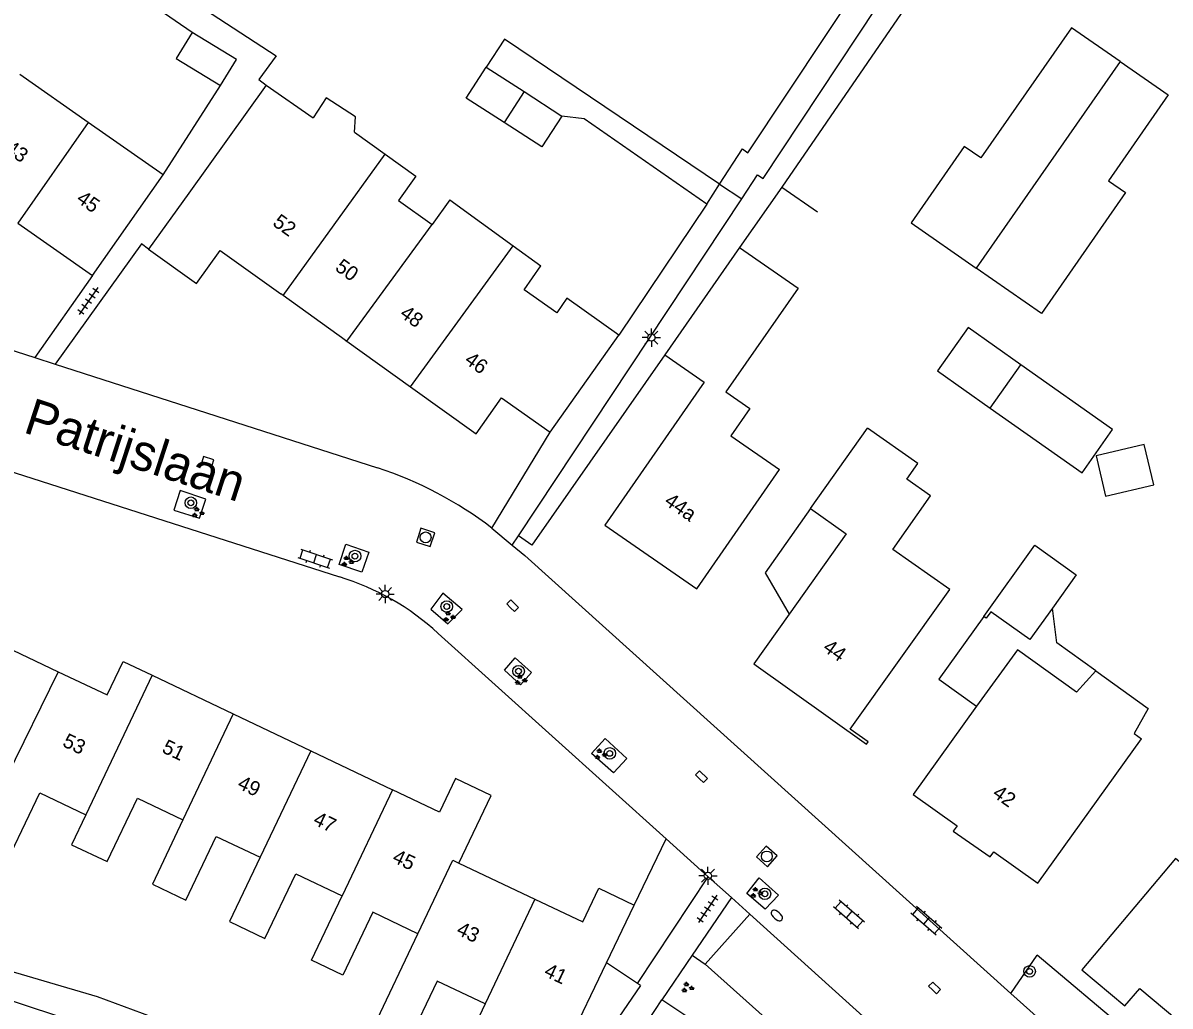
# Model space of a CAD drawing. Extents: x 136000 to 141000, y 400494 to 402006.
# Drawn here: x 137769.2 to 137848.1, y 401752.7 to 401820.4 of the extents above; entities that cross this region are included whole.
import ezdxf

# ---------------------------------------------------------------- set-up
doc = ezdxf.new("R2010")
doc.units = 0
for name, color, linetype in [('gg-afsc-erfafscheiding', 7, 'Continuous'), ('gg-afsc-muur', 7, 'Continuous'), ('gg-anno-huisnummerreeks BGT', 7, 'Continuous'), ('gg-anno-openbare ruimte label', 7, 'Continuous'), ('gg-bbg-bijgebouw', 7, 'Continuous'), ('gg-bbg-gedigitaliseerde bebouwing', 7, 'Continuous'), ('gg-bbg-gedigitaliseerde bijgebouw', 7, 'Continuous'), ('gg-bbg-hoofdgebouw', 7, 'Continuous'), ('gg-bbg-luifel en loopbrug', 7, 'Continuous'), ('gg-bbg-tussenscheiding', 7, 'Continuous'), ('gg-knt-verharding', 7, 'Continuous'), ('gg-knt-verharding nz', 7, 'Continuous'), ('gt-bbg-plantopografie pand', 7, 'Continuous'), ('gt-grn-groengrens', 7, 'Continuous'), ('gt-grn-weggrens', 7, 'Continuous'), ('gt-symb-boom', 7, 'Continuous'), ('gt-symb-brandkraan', 7, 'Continuous'), ('gt-symb-groenvak', 7, 'Continuous'), ('gt-symb-klinker verharding', 7, 'Continuous'), ('gt-symb-kolk', 7, 'Continuous'), ('gt-symb-lichtmast', 7, 'Continuous'), ('gt-symb-rioolschacht', 7, 'Continuous'), ('gt-symb-tegel verharding', 7, 'Continuous')]:
    doc.layers.add(name, color=color, linetype=linetype)

# ---------------------------------------------------------------- blocks, each defined once
blk = doc.blocks.new('gt0-LMAST')
at = {"layer": 'gt-symb-lichtmast'}
for p, q in [((-0.182, 0.173), (-0.447, 0.438)), ((-0.005, 0.246), (-0.005, 0.621)), ((0.172, 0.173), (0.437, 0.438)), ((-0.255, -0.004), (-0.63, -0.004)), ((-0.182, -0.181), (-0.447, -0.446)), ((-0.005, -0.254), (-0.005, -0.629)), ((0.437, -0.446), (0.172, -0.181)), ((0.245, -0.004), (0.62, -0.004))]:
    blk.add_line(p, q, dxfattribs=at)
blk.add_circle((-0.005, -0.004), 0.25, dxfattribs=at)
blk = doc.blocks.new('gt0-BOOM')
at = {"layer": 'gt-symb-boom'}
for radius in [0.4, 0.2]:
    blk.add_circle((0, 0), radius, dxfattribs=at)
blk = doc.blocks.new('gt0-GRVAK')
at = {"layer": 'gt-symb-groenvak'}
for p, q in [((-0.11, 0.189), (-0.228, 0.24)), ((-0.182, 0.153), (0.088, 0.153)), ((-0.091, 0.211), (-0.156, 0.322)), ((-0.047, 0.214), (-0.047, 0.393)), ((-0.004, 0.211), (0.061, 0.322)), ((0.015, 0.189), (0.133, 0.24)), ((0.262, -0.052), (0.197, 0.059)), ((0.305, -0.049), (0.305, 0.13)), ((0.349, -0.052), (0.414, 0.059)), ((-0.245, -0.228), (-0.363, -0.177)), ((-0.318, -0.264), (-0.047, -0.264)), ((-0.226, -0.206), (-0.291, -0.095)), ((-0.183, -0.203), (-0.183, -0.024)), ((-0.139, -0.206), (-0.074, -0.095)), ((-0.12, -0.228), (-0.002, -0.177)), ((0.243, -0.074), (0.125, -0.023)), ((0.17, -0.11), (0.441, -0.11)), ((0.368, -0.074), (0.486, -0.023))]:
    blk.add_line(p, q, dxfattribs=at)
blk = doc.blocks.new('gt0-KOLK')
at = {"layer": 'gt-symb-kolk'}
blk.add_lwpolyline([(0, 0), (0.375, 0), (0.375, 0.4), (-0.375, 0.4), (-0.375, 0), (0, 0)], dxfattribs=at)
blk = doc.blocks.new('gt0-KL1')
at = {"layer": 'gt-symb-klinker verharding'}
for p, q in [((-1.15, 0.3), (1.15, 0.3)), ((-1, -0.3), (-1, 0.3)), ((-0.5, 0.3), (-0.5, 0.45)), ((0, -0.3), (0, 0.3)), ((0.5, 0.3), (0.5, 0.45)), ((1, -0.3), (1, 0.3)), ((-1.15, -0.3), (1.15, -0.3)), ((-0.5, -0.45), (-0.5, -0.3)), ((0.5, -0.45), (0.5, -0.3))]:
    blk.add_line(p, q, dxfattribs=at)
blk = doc.blocks.new('gt0-BR')
at = {"layer": 'gt-symb-brandkraan'}
for centre, radius, start, end in [((-0.244, 0), 0.206, 107.56694, 252.43307), ((0.599, -2.664), 3, 106.89205, 107.56694), ((0, -0.691), 0.938, 73.10799, 106.89205), ((-0.599, -2.664), 3, 72.43309, 73.10799), ((0.244, 0), 0.206, 287.56695, 72.43309), ((0.599, 2.664), 3, 252.43307, 253.10797), ((0, 0.691), 0.938, 253.10797, 286.89206), ((-0.599, 2.664), 3, 286.89206, 287.56695)]:
    blk.add_arc(centre, radius, start, end, dxfattribs=at)
blk = doc.blocks.new('gt0-TEG1')
at = {"layer": 'gt-symb-tegel verharding'}
for p, q in [((-1.125, 0), (1.125, 0)), ((-0.9, -0.25), (-0.9, 0.25)), ((-0.45, -0.25), (-0.45, 0.25)), ((0, -0.25), (0, 0.25)), ((0.45, -0.25), (0.45, 0.25)), ((0.9, -0.25), (0.9, 0.25))]:
    blk.add_line(p, q, dxfattribs=at)
blk = doc.blocks.new('gt0-RS')
at = {"layer": 'gt-symb-rioolschacht'}
blk.add_lwpolyline([(-0.5, -0.5), (0.5, -0.5), (0.5, 0.5), (-0.5, 0.5)], close=True, dxfattribs=at)
blk.add_circle((0, 0), 0.375, dxfattribs=at)

msp = doc.modelspace()

# ---------------------------------------------------------------- linework, layer by layer
at = {"layer": 'gg-afsc-erfafscheiding'}
for p, q in [((137780.876, 401819.745), (137776.992, 401822.397)), ((137778.858, 401809.929), (137782.82, 401816.076)), ((137811.28, 401759.68), (137813.467, 401764.247)), ((137837.19, 401753.606), (137839.014, 401756.232)), ((137859.739, 401738.767), (137839.014, 401756.232)), ((137811.506, 401754.275), (137809.371, 401755.695)), ((137811.705, 401754.142), (137811.506, 401754.275)), ((137790.747, 401719.144), (137813.187, 401753.157)), ((137818.31, 401749.75), (137813.187, 401753.157))]:
    msp.add_line(p, q, dxfattribs=at)
for points in [[(137771.218, 401826.067), (137769.426, 401827.206), (137770.477, 401828.686), (137786.635, 401818.13), (137785.449, 401816.497), (137785.966, 401816.121)], [(137817.149, 401809.288), (137802.355, 401819.277), (137801.104, 401817.349)], [(137816.266, 401807.925), (137807.845, 401813.788), (137806.293, 401813.98)], [(137811.705, 401754.142), (137800.889, 401738.305), (137785.55, 401748.474), (137779.929, 401751.307), (137774.345, 401753.371), (137752.309, 401759.837), (137751.979, 401760.479), (137760.221, 401785.169)], [(137789.112, 401720.207), (137799.793, 401736.553), (137784.157, 401746.769), (137777.66, 401750.03), (137766.125, 401753.85), (137748.493, 401758.699), (137749.088, 401760.026)]]:
    msp.add_lwpolyline(points, dxfattribs=at)
at = {"layer": 'gg-afsc-muur'}
for p, q in [((137821.434, 401809.101), (137818.529, 401804.929)), ((137821.434, 401809.101), (137823.896, 401807.387)), ((137816.266, 401807.925), (137810.213, 401798.912))]:
    msp.add_line(p, q, dxfattribs=at)
at = {"layer": 'gg-bbg-bijgebouw'}
msp.add_lwpolyline([(137838.505, 401777.956), (137835.824, 401779.87), (137835.499, 401779.417), (137835.329, 401779.533)], dxfattribs=at)
at = {"layer": 'gg-bbg-gedigitaliseerde bebouwing'}
for p, q in [((137773.708, 401813.542), (137769.017, 401816.833)), ((137785.966, 401816.121), (137789.193, 401813.857)), ((137778.858, 401809.929), (137773.708, 401813.542)), ((137792.041, 401812.864), (137794.152, 401811.356)), ((137798.598, 401808.209), (137797.371, 401806.52)), ((137798.598, 401808.209), (137802.944, 401805.051)), ((137802.944, 401805.051), (137804.847, 401803.669)), ((137823.405, 401786.964), (137827.323, 401792.512)), ((137815.589, 401781.449), (137821.268, 401789.65)), ((137841.702, 401774.339), (137843.041, 401775.794))]:
    msp.add_line(p, q, dxfattribs=at)
for points in [[(137792.041, 401812.864), (137792.106, 401813.939), (137790.093, 401815.245), (137789.193, 401813.857)], [(137794.152, 401811.356), (137796.263, 401809.848), (137795.064, 401808.168), (137797.371, 401806.52)], [(137818.529, 401804.929), (137822.562, 401802.13), (137817.591, 401795.002), (137819.229, 401793.861), (137817.918, 401791.977), (137821.268, 401789.65)], [(137810.213, 401798.912), (137806.641, 401801.441), (137805.945, 401800.451), (137803.696, 401802.033), (137804.847, 401803.669)], [(137826.144, 401771.79), (137832.986, 401781.401), (137829.068, 401784.16), (137831.671, 401787.849), (137830.042, 401788.997), (137830.798, 401790.06), (137827.323, 401792.512)], [(137843.041, 401775.794), (137846.635, 401773.217), (137845.687, 401771.483), (137846.19, 401771.122)], [(137768.099, 401768.49), (137766.127, 401764.348), (137768.4, 401763.266), (137770.374, 401767.412), (137773.557, 401765.896)], [(137773.557, 401765.896), (137772.573, 401763.83), (137775.013, 401762.669), (137777.095, 401767.041), (137780.232, 401765.548)], [(137780.232, 401765.548), (137778.128, 401761.129), (137780.436, 401760.03), (137782.519, 401764.405), (137785.536, 401762.968)], [(137785.536, 401762.968), (137783.432, 401758.55), (137785.873, 401757.388), (137787.988, 401761.831), (137791.185, 401760.309)], [(137796.391, 401757.705), (137793.288, 401759.182), (137791.228, 401754.856), (137789.077, 401755.88), (137791.185, 401760.309)], [(137801.025, 401752.877), (137797.719, 401754.451), (137795.724, 401750.259), (137793.378, 401751.376), (137796.391, 401757.705)], [(137801.025, 401752.877), (137799, 401748.626), (137801.32, 401747.521), (137803.316, 401751.713), (137806.694, 401750.104), (137809.371, 401755.695)]]:
    msp.add_lwpolyline(points, dxfattribs=at)
at = {"layer": 'gg-bbg-gedigitaliseerde bijgebouw'}
for p, q in [((137801.104, 401817.349), (137803.699, 401815.664)), ((137803.699, 401815.664), (137806.293, 401813.98)), ((137835.773, 401793.89), (137837.874, 401796.866)), ((137840.047, 401780.116), (137838.505, 401777.956))]:
    msp.add_line(p, q, dxfattribs=at)
for points in [[(137780.876, 401819.745), (137779.772, 401817.953), (137782.82, 401816.076)], [(137782.82, 401816.076), (137783.924, 401817.868), (137780.876, 401819.745)], [(137844.707, 401817.735), (137841.358, 401820.065), (137835.119, 401811.097), (137833.983, 401811.888), (137830.324, 401806.63), (137834.809, 401803.509)], [(137802.32, 401813.541), (137799.726, 401815.225), (137801.104, 401817.349)], [(137844.707, 401817.735), (137848.006, 401815.439), (137843.916, 401809.524), (137845.085, 401808.712), (137839.294, 401800.389), (137834.809, 401803.509)], [(137806.293, 401813.98), (137804.914, 401811.857), (137802.32, 401813.541)], [(137837.874, 401796.866), (137834.252, 401799.424), (137832.15, 401796.447), (137835.773, 401793.89)], [(137835.329, 401779.533), (137838.842, 401784.453), (137841.691, 401782.418), (137840.047, 401780.116)]]:
    msp.add_lwpolyline(points, dxfattribs=at)
at = {"layer": 'gg-bbg-hoofdgebouw'}
for p, q in [((137774.01, 401803.02), (137778.858, 401809.929)), ((137768.878, 401806.621), (137774.01, 401803.02)), ((137818.529, 401804.929), (137813.385, 401797.556)), ((137787.116, 401801.635), (137786.972, 401801.739)), ((137791.391, 401798.569), (137787.116, 401801.635)), ((137805.49, 401792.221), (137810.213, 401798.912)), ((137791.391, 401798.569), (137791.504, 401798.488)), ((137791.504, 401798.488), (137795.876, 401795.352)), ((137813.385, 401797.556), (137816.097, 401795.67)), ((137802.141, 401794.584), (137805.49, 401792.221)), ((137766.007, 401778.416), (137771.634, 401775.744)), ((137778.116, 401775.495), (137783.695, 401772.838)), ((137783.695, 401772.838), (137789.039, 401770.294)), ((137789.039, 401770.294), (137794.657, 401767.619)), ((137799.21, 401762.57), (137804.448, 401760.083)), ((137809.371, 401755.695), (137811.28, 401759.68))]:
    msp.add_line(p, q, dxfattribs=at)
for points in [[(137785.966, 401816.121), (137780.632, 401808.684), (137777.864, 401804.826)], [(137777.864, 401804.826), (137781.163, 401802.46), (137782.795, 401804.735), (137786.972, 401801.739)], [(137816.097, 401795.67), (137809.251, 401785.838), (137815.589, 401781.449)], [(137795.876, 401795.352), (137800.404, 401792.104), (137802.141, 401794.584)], [(137823.405, 401786.964), (137825.856, 401785.234), (137821.946, 401779.709)], [(137821.946, 401779.709), (137819.516, 401776.276), (137827.253, 401770.752), (137827.372, 401770.918), (137826.144, 401771.79)], [(137841.702, 401774.339), (137837.64, 401777.251), (137834.84, 401773.364)], [(137771.634, 401775.744), (137775.01, 401774.14), (137776.11, 401776.45), (137778.116, 401775.495)], [(137834.84, 401773.364), (137830.463, 401767.288), (137833.494, 401765.134), (137833.234, 401764.769), (137835.764, 401762.996), (137836.017, 401763.356), (137839.04, 401761.186), (137846.19, 401771.122)], [(137799.21, 401762.57), (137801.43, 401767.23), (137798.98, 401768.39), (137797.89, 401766.08), (137794.657, 401767.619)], [(137804.448, 401760.083), (137807.74, 401758.52), (137808.85, 401760.84), (137811.28, 401759.68)]]:
    msp.add_lwpolyline(points, dxfattribs=at)
at = {"layer": 'gg-bbg-luifel en loopbrug'}
for points in [[(137835.773, 401793.89), (137842.093, 401789.428), (137844.195, 401792.404), (137837.874, 401796.866)], [(137843.715, 401787.812), (137847.034, 401788.602), (137846.372, 401791.384), (137843.052, 401790.593), (137843.715, 401787.812)], [(137823.405, 401786.964), (137820.282, 401782.54), (137821.946, 401779.709)], [(137843.041, 401775.794), (137840.349, 401777.724), (137840.047, 401780.116)], [(137835.329, 401779.533), (137832.242, 401775.227), (137834.84, 401773.364)]]:
    msp.add_lwpolyline(points, dxfattribs=at)
at = {"layer": 'gg-bbg-tussenscheiding'}
for p, q in [((137844.707, 401817.735), (137834.809, 401803.509)), ((137803.699, 401815.664), (137802.32, 401813.541)), ((137773.708, 401813.542), (137768.878, 401806.621)), ((137787.116, 401801.635), (137794.152, 401811.356)), ((137791.504, 401798.488), (137797.371, 401806.52)), ((137795.876, 401795.352), (137802.944, 401805.051)), ((137771.634, 401775.744), (137768.099, 401768.49)), ((137778.116, 401775.495), (137773.557, 401765.896)), ((137783.695, 401772.838), (137780.232, 401765.548)), ((137789.039, 401770.294), (137785.536, 401762.968)), ((137794.657, 401767.619), (137791.185, 401760.309)), ((137804.448, 401760.083), (137801.025, 401752.877))]:
    msp.add_line(p, q, dxfattribs=at)
msp.add_lwpolyline([(137796.391, 401757.705), (137798.8, 401762.765), (137799.21, 401762.57)], dxfattribs=at)
at = {"layer": 'gg-knt-verharding'}
for p, q in [((137803.307, 401785.103), (137818.681, 401808.296)), ((137744.5, 401805.6), (137770.043, 401797.366)), ((137774.01, 401803.02), (137770.043, 401797.366)), ((137770.043, 401797.366), (137771.44, 401796.916)), ((137771.44, 401796.916), (137793.612, 401789.769)), ((137801.493, 401785.628), (137805.49, 401792.221)), ((137762.278, 401791.469), (137791, 401782.26)), ((137801.493, 401785.628), (137802.881, 401784.461)), ((137802.881, 401784.461), (137803.307, 401785.103)), ((137797.779, 401778.381), (137813.467, 401764.247)), ((137813.467, 401764.247), (137816.377, 401761.626)), ((137811.506, 401754.275), (137816.377, 401761.626)), ((137816.377, 401761.626), (137817.964, 401760.196)), ((137817.964, 401760.196), (137815.27, 401756.226)), ((137817.964, 401760.196), (137819.243, 401759.044)), ((137816.17, 401755.615), (137819.243, 401759.044)), ((137815.27, 401756.226), (137813.187, 401753.157)), ((137829.669, 401743.53), (137816.17, 401755.615))]:
    msp.add_line(p, q, dxfattribs=at)
for points in [[(137817.149, 401809.288), (137818.724, 401811.719), (137819.093, 401811.462), (137840.788, 401844.131)], [(137818.681, 401808.296), (137819.772, 401809.942), (137820.147, 401809.693), (137842.333, 401843.186)], [(137777.864, 401804.826), (137777.368, 401805.182), (137771.44, 401796.916)], [(137780.042, 401788.207), (137779.608, 401786.87), (137781.377, 401786.298), (137781.805, 401787.624), (137780.042, 401788.207)], [(137793.029, 401783.969), (137792.53, 401782.588), (137790.968, 401783.12), (137791.437, 401784.524), (137793.029, 401783.969)], [(137802.881, 401784.461), (137803.744, 401783.737), (137837.19, 401753.606)], [(137799.116, 401779.696), (137799.437, 401780.027), (137798.122, 401781.153), (137797.279, 401780.046), (137798.466, 401779.026), (137799.116, 401779.696)], [(137804.219, 401775.685), (137803.45, 401774.833), (137802.358, 401775.847), (137803.081, 401776.689), (137804.219, 401775.685)], [(137810.78, 401769.775), (137809.852, 401768.777), (137808.35, 401770.113), (137809.271, 401771.147), (137810.78, 401769.775)], [(137820.281, 401759.389), (137819.024, 401760.481), (137819.879, 401761.567), (137821.214, 401760.374), (137820.281, 401759.389)], [(137840.962, 401750.236), (137840.473, 401750.648), (137837.19, 401753.606)]]:
    msp.add_lwpolyline(points, dxfattribs=at)
for centre, radius, start, end in [((137785.294, 401764.368), 26.728, 52.69396, 71.86749), ((137786.042, 401765.732), 17.256, 47.14135, 73.30155)]:
    msp.add_arc(centre, radius, start, end, dxfattribs=at)
at = {"layer": 'gg-knt-verharding nz'}
msp.add_line((137819.243, 401759.044), (137832.736, 401746.888), dxfattribs=at)
at = {"layer": 'gt-bbg-plantopografie pand'}
msp.add_lwpolyline([(137856.507, 401754.079), (137860.729, 401759.615), (137856.4, 401763.27), (137852.938, 401759.162), (137848.527, 401762.88), (137842.081, 401755.23), (137845.041, 401752.736), (137846.062, 401753.947), (137850.436, 401750.261), (137854.435, 401755.624), (137856.507, 401754.079)], dxfattribs=at)
at = {"layer": 'gt-grn-groengrens'}
for p, q in [((137844.089, 401842.112), (137821.434, 401809.101)), ((137815.27, 401756.226), (137816.17, 401755.615))]:
    msp.add_line(p, q, dxfattribs=at)
msp.add_lwpolyline([(137813.385, 401797.556), (137804.242, 401784.451), (137803.307, 401785.103)], dxfattribs=at)
at = {"layer": 'gt-grn-weggrens'}
for p, q in [((137816.266, 401807.925), (137817.149, 401809.288)), ((137817.149, 401809.288), (137818.681, 401808.296))]:
    msp.add_line(p, q, dxfattribs=at)

# ---------------------------------------------------------------- block references
at = {"layer": 'gt-symb-boom'}
for p in [(137780.773, 401787.366), (137792.067, 401783.698), (137798.381, 401780.231), (137809.593, 401770.12), (137820.272, 401760.453), (137838.485, 401755.116)]:
    msp.add_blockref('gt0-BOOM', p, dxfattribs=at)
at = {"layer": 'gt-symb-boom', "rotation": -42.04255015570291}
msp.add_blockref('gt0-BOOM', (137803.319, 401775.777), dxfattribs=at)
at = {"layer": 'gt-symb-brandkraan', "rotation": 138.00000872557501}
msp.add_blockref('gt0-BR', (137821.092, 401758.966), dxfattribs=at)
at = {"layer": 'gt-symb-groenvak'}
for p in [(137781.236, 401786.692), (137791.53, 401783.327), (137798.52, 401779.526), (137803.454, 401775.173), (137808.94, 401770.055), (137819.669, 401760.522), (137814.929, 401754.002)]:
    msp.add_blockref('gt0-GRVAK', p, dxfattribs=at)
at = {"layer": 'gt-symb-klinker verharding'}
for p, rotation in [((137789.329, 401783.519), -18.670583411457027), ((137826.05, 401759.032), 139.01346679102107), ((137831.377, 401758.6), 138.93264367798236)]:
    msp.add_blockref('gt0-KL1', p, dxfattribs=dict(at, rotation=rotation))
at = {"layer": 'gt-symb-kolk'}
for p, rotation in [((137781.879, 401790.061), -17.275420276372), ((137802.774, 401780.144), -44.35170201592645), ((137815.768, 401768.372), -44.35170201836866), ((137831.803, 401753.837), -44.35170201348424)]:
    msp.add_blockref('gt0-KOLK', p, dxfattribs=dict(at, rotation=rotation))
at = {"layer": 'gt-symb-lichtmast'}
for p in [(137812.463, 401798.741), (137794.15, 401781.093)]:
    msp.add_blockref('gt0-LMAST', p, dxfattribs=at)
at = {"layer": 'gt-symb-lichtmast', "rotation": 90}
msp.add_blockref('gt0-LMAST', (137816.349, 401761.704), dxfattribs=at)
at = {"layer": 'gt-symb-rioolschacht'}
for p, rotation in [((137796.922, 401784.988), -18.00007459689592), ((137820.403, 401763.027), -42.04255015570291)]:
    msp.add_blockref('gt0-RS', p, dxfattribs=dict(at, rotation=rotation))
at = {"layer": 'gt-symb-tegel verharding'}
for p, rotation in [((137773.728, 401801.253), -125.02487327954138), ((137816.324, 401759.423), -123.91251258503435)]:
    msp.add_blockref('gt0-TEG1', p, dxfattribs=dict(at, rotation=rotation))

# ---------------------------------------------------------------- texts
at = {"layer": 'gg-anno-huisnummerreeks BGT'}
for s, rotation, p in [('43', 325, (137767.911, 401811.575)), ('45', 325, (137772.834, 401808.121)), ('52', 324.4, (137786.334, 401806.503)), ('50', 324.4, (137790.63, 401803.421)), ('48', 324.4, (137795.084, 401800.227)), ('46', 324.4, (137799.534, 401797.035)), ('44a', 325.3, (137813.279, 401787.306)), ('44', 324.5, (137824.189, 401777.24)), ('53', 334.6, (137771.877, 401770.645)), ('51', 334.5, (137778.718, 401770.225)), ('49', 334.5, (137783.91, 401767.753)), ('42', 325, (137835.858, 401767.205)), ('47', 334.5, (137789.119, 401765.272)), ('45', 334.5, (137794.567, 401762.679)), ('43', 334.6, (137798.98, 401757.697)), ('41', 334.6, (137805.005, 401754.836))]:
    msp.add_text(s, height=1, rotation=rotation, dxfattribs=at).set_placement(p)
at = {"layer": 'gg-anno-openbare ruimte label'}
msp.add_text('Patrijslaan', height=2.5, rotation=342, dxfattribs=at).set_placement((137769.166, 401792.236))

doc.saveas('drawing.dxf')
